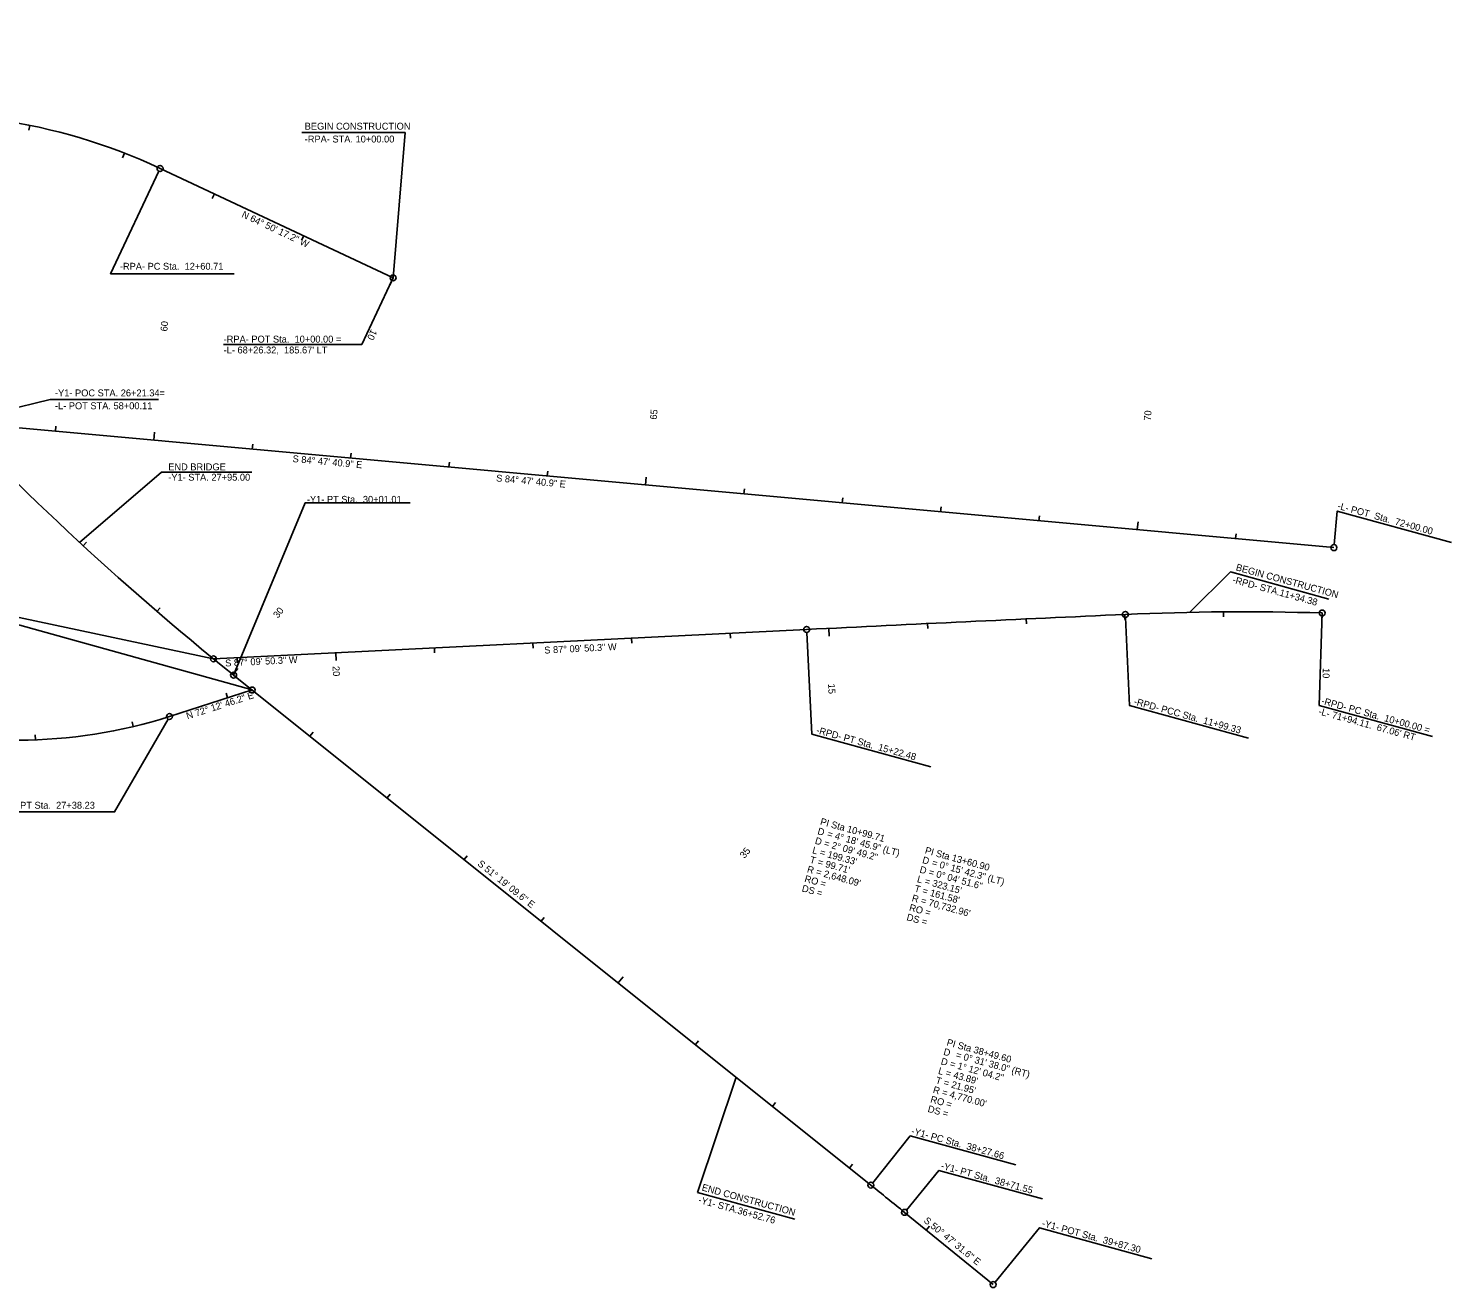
# Model space of a CAD drawing. Extents: x 1636713 to 1642783, y 841520 to 844371.
# Drawn here: x 1641342 to 1642783, y 841520 to 842796 of the extents above; entities that cross this region are included whole.
import ezdxf

# ---------------------------------------------------------------- set-up
doc = ezdxf.new("R2010")
doc.units = 0
for name, color, linetype in [('COGO Default Chain', 7, 'Continuous'), ('Prop Horizontal Alignment', 7, 'Continuous'), ('Prop Horizontal Alignment Curve and Spiral Data', 7, 'Continuous'), ('Prop Horizontal Alignment Direction Label', 7, 'Continuous'), ('Prop Horizontal Alignment Station Label', 7, 'Continuous'), ('Prop Horizontal Alignment Tick Label', 7, 'Continuous'), ('Prop Horizontal Alignment Tick Large', 7, 'Continuous'), ('Prop Horizontal Alignment Tick Small', 7, 'Continuous')]:
    doc.layers.add(name, color=color, linetype=linetype)

msp = doc.modelspace()

# ---------------------------------------------------------------- linework, layer by layer
at = {"layer": 'COGO Default Chain'}
for p, q in [((1641549.8, 842140.7), (1642195.1, 841624.1)), ((1642229.3, 841596.5), (1642319, 841523.3))]:
    msp.add_line(p, q, dxfattribs=at)
for centre, radius, start, end in [((1643339.8, 844376.5), 2864, 213.4979, 231.3193), ((1639214, 837900.4), 4770, 50.7921, 51.3193)]:
    msp.add_arc(centre, radius, start, end, dxfattribs=at)
at = {"layer": 'Prop Horizontal Alignment'}
for p, q in [((1641711.3, 842543.2), (1641475.3, 842654)), ((1641226.3, 842400.9), (1642664.1, 842269.9)), ((1642130.1, 842187), (1641529.4, 842157.2)), ((1641549.8, 842140.7), (1642195.1, 841624.1)), ((1641484.8, 842098.8), (1641568.6, 842125.7)), ((1641484.8, 842098.8), (1641568.6, 842125.7)), ((1642229.3, 841596.5), (1642319, 841523.3))]:
    msp.add_line(p, q, dxfattribs=at)
for centre, radius, start, end in [((1643339.8, 844376.5), 2864, 213.4979, 231.3193), ((1641228.7, 842129.1), 580, 64.8381, 98.9679), ((1645629.8, 771540.6), 70733, 92.574274, 92.836038), ((1642571.8, 839556.8), 2648.1, 88.2615, 92.5743), ((1641332.1, 842574.9), 500, 252.1928, 287.7872), ((1641332.1, 842574.9), 500, 252.1928, 287.7872), ((1639214, 837900.4), 4770, 50.7921, 51.3193)]:
    msp.add_arc(centre, radius, start, end, dxfattribs=at)
at = {"layer": 'Prop Horizontal Alignment Station Label'}
for p, q in [((1641720.8, 842690.3), (1641618.8, 842690.3)), ((1641473.6, 842420.1), (1641365.9, 842420.1)), ((1642658.9, 842217.8), (1642560.6, 842244.9)), ((1642118, 841589.6), (1642019.7, 841616.7))]:
    msp.add_line(p, q, dxfattribs=at)
for points in [[(1641618.8, 842690.3), (1641723.5, 842690.3), (1641711.3, 842543.2)], [(1641474.1, 842651.3), (1641425.2, 842547.4), (1641550.2, 842547.4)], [(1641710, 842540.5), (1641679.6, 842475.6), (1641539.6, 842475.6)], [(1641473.6, 842420.1), (1641364.1, 842420.1), (1641270, 842396.9)], [(1641393.7, 842275.2), (1641476.7, 842346.4), (1641568.1, 842346.4)], [(1641728.7, 842315.3), (1641622.4, 842315.3), (1641549.8, 842140.7)], [(1642664.4, 842272.9), (1642667.5, 842306.9), (1642783.2, 842275.1)], [(1642658.9, 842217.8), (1642559.4, 842245.2), (1642517.8, 842204.3)], [(1641227.3, 842220.6), (1641230.6, 842220.6), (1641529.4, 842157.2)], [(1642652.2, 842203.7), (1642649.3, 842110.1), (1642763.9, 842078.5)], [(1641292.1, 842193.5), (1641327.2, 842192.9), (1641568.6, 842125.7)], [(1642453, 842199.2), (1642457, 842110.1), (1642577.6, 842076.9)], [(1642130.3, 842184), (1642135.4, 842081), (1642255.9, 842047.9)], [(1641483.5, 842096.2), (1641429.2, 842002.1), (1641299.2, 842002.1)], [(1642019.7, 841616.7), (1642058.6, 841733.4)], [(1642197, 841626.4), (1642235.1, 841674), (1642342.1, 841644.6)], [(1642231.2, 841598.8), (1642264, 841639), (1642369.1, 841610.1)], [(1642320.9, 841525.7), (1642365.9, 841580.9), (1642479.8, 841549.5)]]:
    msp.add_lwpolyline(points, dxfattribs=at)
for centre in [(1641475.3, 842654), (1641711.3, 842543.2), (1642664.1, 842269.9), (1642452.9, 842202.2), (1642652.2, 842203.7), (1642130.1, 842187), (1641529.4, 842157.2), (1641549.8, 842140.7), (1641568.6, 842125.7), (1641484.8, 842098.8), (1642195.1, 841624.1), (1642229.3, 841596.5), (1642319, 841523.3)]:
    msp.add_circle(centre, 3, dxfattribs=at)
at = {"layer": 'Prop Horizontal Alignment Tick Large'}
for p, q in [((1641711.3, 842543.2), (1641707.9, 842535.9)), ((1641469.1, 842378.8), (1641469.8, 842386.8)), ((1641967, 842333.4), (1641967.7, 842341.4)), ((1642465, 842288.1), (1642465.7, 842296)), ((1642652.2, 842203.7), (1642651.9, 842195.7)), ((1642152.6, 842188.1), (1642153, 842180.1)), ((1641653.2, 842163.3), (1641653.6, 842155.4)), ((1641549, 842141.4), (1641554, 842147.6)), ((1641939.4, 841828.9), (1641944.4, 841835.1))]:
    msp.add_line(p, q, dxfattribs=at)
at = {"layer": 'Prop Horizontal Alignment Tick Small'}
for p, q in [((1641343.4, 842697.6), (1641342.4, 842692.7)), ((1641439.2, 842669.5), (1641437.4, 842664.9)), ((1641530.3, 842628.2), (1641528.2, 842623.7)), ((1641620.8, 842585.7), (1641618.7, 842581.2)), ((1641369.5, 842387.9), (1641369.9, 842392.9)), ((1641568.7, 842369.7), (1641569.1, 842374.7)), ((1641668.3, 842360.7), (1641668.7, 842365.6)), ((1641767.8, 842351.6), (1641768.3, 842356.6)), ((1641867.4, 842342.5), (1641867.9, 842347.5)), ((1642066.6, 842324.4), (1642067.1, 842329.3)), ((1642166.2, 842315.3), (1642166.6, 842320.3)), ((1642265.8, 842306.2), (1642266.2, 842311.2)), ((1642365.4, 842297.1), (1642365.8, 842302.1)), ((1641397.4, 842271.8), (1641400.8, 842275.4)), ((1642564.5, 842279), (1642565, 842284)), ((1641472.1, 842205.2), (1641475.4, 842209)), ((1642452.2, 842202.2), (1642452.5, 842197.2)), ((1642552.2, 842204.8), (1642552.2, 842199.8)), ((1642252.4, 842192.9), (1642252.7, 842187.9)), ((1642352.3, 842197.6), (1642352.6, 842192.6)), ((1641952.8, 842178.2), (1641953.1, 842173.2)), ((1642052.7, 842183.1), (1642052.9, 842178.1)), ((1641753.1, 842168.3), (1641753.3, 842163.3)), ((1641852.9, 842173.2), (1641853.2, 842168.2)), ((1641553.3, 842158.4), (1641553.5, 842153.4)), ((1641543.7, 842117.7), (1641542.1, 842122.5)), ((1641448, 842088.6), (1641446.9, 842093.4)), ((1641349.1, 842075.2), (1641348.9, 842080.2)), ((1641627.1, 842078.9), (1641630.2, 842082.8)), ((1641705.2, 842016.4), (1641708.3, 842020.3)), ((1641783.2, 841953.9), (1641786.4, 841957.8)), ((1641861.3, 841891.4), (1641864.4, 841895.3)), ((1642017.4, 841766.4), (1642020.5, 841770.3)), ((1642095.5, 841703.9), (1642098.6, 841707.8)), ((1642173.6, 841641.4), (1642176.7, 841645.3)), ((1642251.3, 841578.5), (1642254.5, 841582.4))]:
    msp.add_line(p, q, dxfattribs=at)

# ---------------------------------------------------------------- texts
at = {"layer": 'Prop Horizontal Alignment Curve and Spiral Data'}
for s, p in [('D ', (1642140.6, 841979.7)), ('PI Sta 10+99.71', (1642143.3, 841989.4)), ('D = 2%%d 09\' 49.2"', (1642138, 841970)), ('= 4%%d 18\' 45.9" (LT)', (1642150.3, 841977)), ("T = 99.71'", (1642132.7, 841950.7)), ("L = 199.33'", (1642135.3, 841960.4)), ('PI Sta 13+60.90', (1642249.4, 841960.2)), ("R = 2,648.09'", (1642130, 841941.1)), ('D = 0%%d 04\' 51.6"', (1642244, 841940.8)), ('D ', (1642246.7, 841950.5)), ('= 0%%d 15\' 42.3" (LT)', (1642256.3, 841947.8)), ('DS =', (1642124.7, 841921.8)), ('RO =', (1642127.4, 841931.5)), ("L = 323.15'", (1642241.4, 841931.2)), ("R = 70,732.96'", (1642236.1, 841911.9)), ("T = 161.58'", (1642238.7, 841921.6)), ('RO =', (1642233.4, 841902.3)), ('DS =', (1642230.8, 841892.6)), ('PI Sta 38+49.60', (1642271.4, 841765.7)), ('D', (1642268.1, 841756.2)), ('= 0%%d 31\' 38.0" (RT)', (1642280.6, 841753.1)), ("L = 43.89'", (1642262.8, 841736.9)), ('D = 1%%d 12\' 04.2"', (1642265.5, 841746.6)), ("T = 21.95'", (1642260.2, 841727.3)), ('RO =', (1642254.9, 841708)), ("R = 4,770.00'", (1642257.5, 841717.7)), ('DS =', (1642252.2, 841698.4))]:
    msp.add_text(s, height=7, rotation=344.6135, dxfattribs=at).set_placement(p)
at = {"layer": 'Prop Horizontal Alignment Direction Label'}
for s, rotation, p in [('N 64%%d 50\' 17.2" W', 334.8381, (1641557.3, 842605)), ('S 84%%d 47\' 40.9" E', 354.7947, (1641609.3, 842356.6)), ('S 84%%d 47\' 40.9" E', 354.7947, (1641815.4, 842337)), ('S 87%%d 09\' 50.3" W', 2.836, (1641541.4, 842149.4)), ('S 87%%d 09\' 50.3" W', 2.836, (1641864.6, 842162.5)), ('N 72%%d 12\' 46.2" E', 17.7872, (1641503.1, 842095.8)), ('S 51%%d 19\' 09.6" E', 321.3193, (1641796.2, 841948.5)), ('S 50%%d 47\' 31.6" E', 320.7921, (1642248.1, 841587.1))]:
    msp.add_text(s, height=7, rotation=rotation, dxfattribs=at).set_placement(p)
at = {"layer": 'Prop Horizontal Alignment Station Label'}
for s, p in [('BEGIN CONSTRUCTION', (1641621.8, 842693.3)), ('-RPA- STA. 10+00.00', (1641621.8, 842680.3)), ('-RPA- POT Sta.  10+00.00 =', (1641539.7, 842477.6)), ("-L- 68+26.32,  185.67' LT", (1641539.7, 842466.6)), ('-Y1- POC STA. 26+21.34=', (1641368.9, 842423.1)), ('-L- POT STA. 58+00.11', (1641368.9, 842410.1)), ('-Y1- PT Sta.  30+01.01', (1641624, 842315.3))]:
    msp.add_text(s, height=7, dxfattribs=at).set_placement(p)
for s, rotation, p in [('-RPA- PC Sta.  12+60.71', 360, (1641434.6, 842551.4)), ('END BRIDGE', 360, (1641483.6, 842348.2)), ('-Y1- STA. 27+95.00', 360, (1641483.6, 842337.7)), ('-L- POT  Sta.  72+00.00', 344.6135, (1642667.1, 842309.3)), ('BEGIN CONSTRUCTION', 344.6135, (1642564.3, 842247)), ('-RPD- STA.11+34.38', 344.6135, (1642560.8, 842234.4)), ('-RPD- PCC Sta.  11+99.33', 344.6135, (1642460.9, 842111.1)), ('-RPD- PC Sta.  10+00.00 =', 344.6135, (1642650.8, 842111.7)), ("-L- 71+94.11.  67.06' RT", 344.6135, (1642647.9, 842101.1)), ('-RPD- PT Sta.  15+22.48', 344.6135, (1642139.3, 842082)), ('-RPC- PT Sta.  27+38.23', 360, (1641305, 842005.4)), ('-Y1- PC Sta.  38+27.66', 344.6135, (1642235.6, 841675.9)), ('-Y1- PT Sta.  38+71.55', 344.6135, (1642265.5, 841640.7)), ('-Y1- STA.36+52.76', 344.6135, (1642019.9, 841606.2)), ('END CONSTRUCTION', 344.6135, (1642023.4, 841618.8)), ('-Y1- POT Sta.  39+87.30', 344.6135, (1642367.8, 841582.5))]:
    msp.add_text(s, height=7, rotation=rotation, dxfattribs=at).set_placement(p)
at = {"layer": 'Prop Horizontal Alignment Tick Label'}
for s, rotation, p in [('60', 84.7947, (1641482.6, 842488.7)), ('10', 244.8381, (1641689.2, 842491.6)), ('65', 84.7947, (1641978.3, 842399.3)), ('70', 84.7947, (1642478.5, 842398.2)), ('30', 51.299, (1641594.6, 842197.8)), ('20', 272.836, (1641650, 842149.8)), ('10', 268.2615, (1642652.9, 842148)), ('15', 272.8178, (1642151.8, 842131.9)), ('35', 51.3193, (1642067.2, 841954.5))]:
    msp.add_text(s, height=7, rotation=rotation, dxfattribs=at).set_placement(p)

doc.saveas('drawing.dxf')
